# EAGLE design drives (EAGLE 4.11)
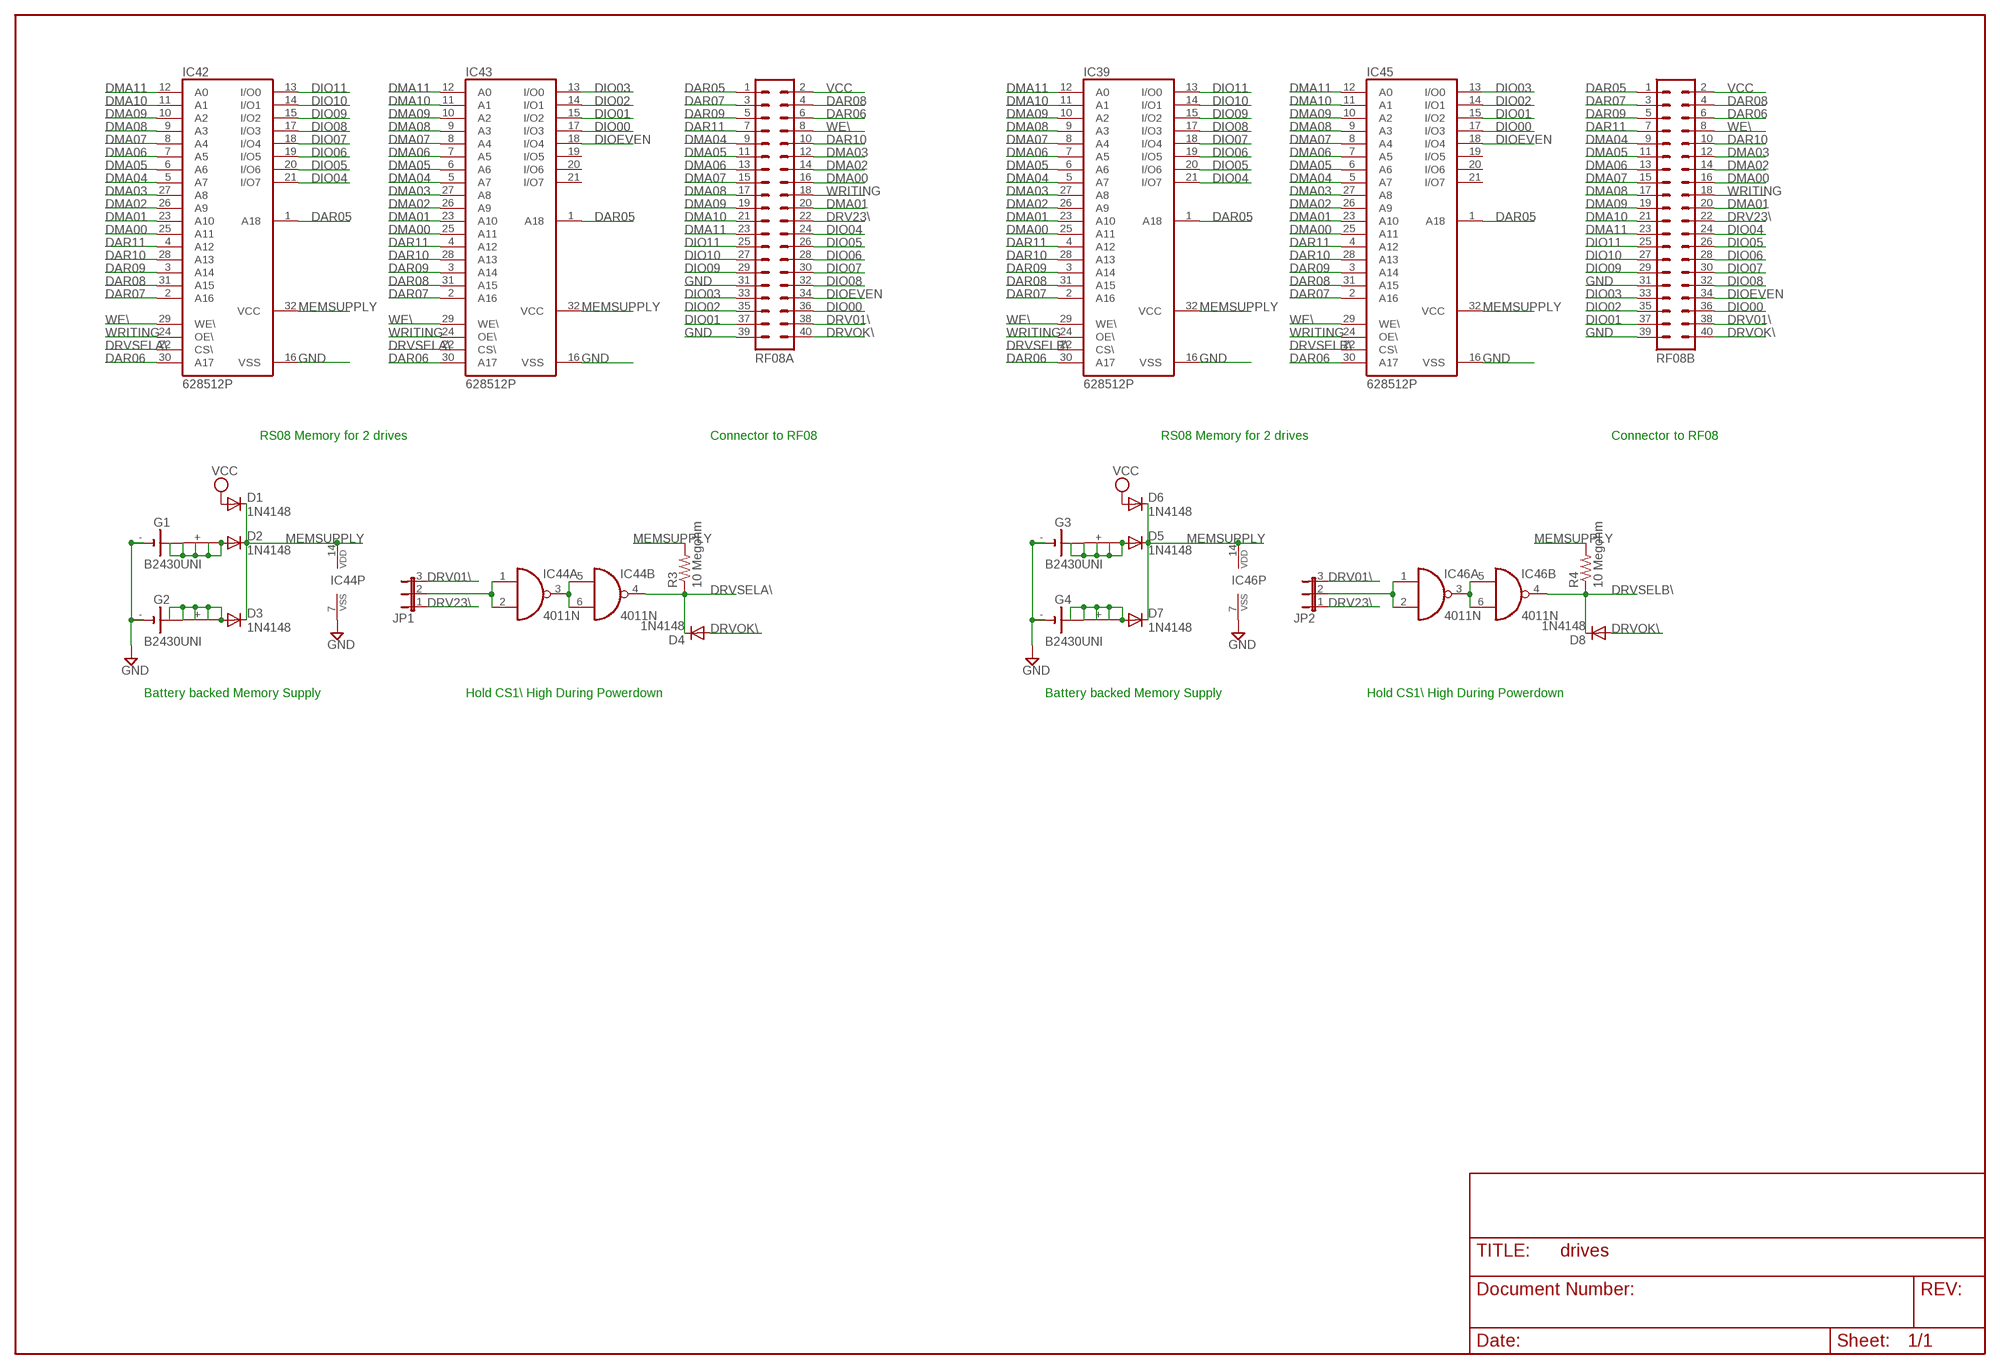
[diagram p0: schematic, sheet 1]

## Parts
D1  1N4148  [DO35-10]
D2  1N4148  [DO35-10]
D3  1N4148  [DO35-10]
D4  1N4148  [DO35-10]
D5  1N4148  [DO35-10]
D6  1N4148  [DO35-10]
D7  1N4148  [DO35-10]
D8  1N4148  [DO35-10]
G1  B2430UNI  [B2430UNI]
G2  B2430UNI  [B2430UNI]
G3  B2430UNI  [B2430UNI]
G4  B2430UNI  [B2430UNI]
IC39  628512P  [DIL32]
IC42  628512P  [DIL32]
IC43  628512P  [DIL32]
IC44  4011N  [DIL14]
IC45  628512P  [DIL32]
IC46  4011N  [DIL14]
JP1  JP2E  [JP2]
JP2  JP2E  [JP2]
R3  10 Megohm  R-US_0207/10  [0207/10]
R4  10 Megohm  R-US_0207/10  [0207/10]
RF08A  MA20-2  [MA20-2]
RF08B  MA20-2  [MA20-2]

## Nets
DAR05: IC39.1(A18) IC42.1(A18) IC43.1(A18) IC45.1(A18) RF08A.1 RF08B.1
DAR06: IC39.30(A17) IC42.30(A17) IC43.30(A17) IC45.30(A17) RF08A.6 RF08B.6
DAR07: IC39.2(A16) IC42.2(A16) IC43.2(A16) IC45.2(A16) RF08A.3 RF08B.3
DAR08: IC39.31(A15) IC42.31(A15) IC43.31(A15) IC45.31(A15) RF08A.4 RF08B.4
DAR09: IC39.3(A14) IC42.3(A14) IC43.3(A14) IC45.3(A14) RF08A.5 RF08B.5
DAR10: IC39.28(A13) IC42.28(A13) IC43.28(A13) IC45.28(A13) RF08A.10 RF08B.10
DAR11: IC39.4(A12) IC42.4(A12) IC43.4(A12) IC45.4(A12) RF08A.7 RF08B.7
DIO00: IC43.17(I/O3) IC45.17(I/O3) RF08A.36 RF08B.36
DIO01: IC43.15(I/O2) IC45.15(I/O2) RF08A.37 RF08B.37
DIO02: IC43.14(I/O1) IC45.14(I/O1) RF08A.35 RF08B.35
DIO03: IC43.13(I/O0) IC45.13(I/O0) RF08A.33 RF08B.33
DIO04: IC39.21(I/O7) IC42.21(I/O7) RF08A.24 RF08B.24
DIO05: IC39.20(I/O6) IC42.20(I/O6) RF08A.26 RF08B.26
DIO06: IC39.19(I/O5) IC42.19(I/O5) RF08A.28 RF08B.28
DIO07: IC39.18(I/O4) IC42.18(I/O4) RF08A.30 RF08B.30
DIO08: IC39.17(I/O3) IC42.17(I/O3) RF08A.32 RF08B.32
DIO09: IC39.15(I/O2) IC42.15(I/O2) RF08A.29 RF08B.29
DIO10: IC39.14(I/O1) IC42.14(I/O1) RF08A.27 RF08B.27
DIO11: IC39.13(I/O0) IC42.13(I/O0) RF08A.25 RF08B.25
DIOEVEN: IC43.18(I/O4) IC45.18(I/O4) RF08A.34 RF08B.34
DMA00: IC39.25(A11) IC42.25(A11) IC43.25(A11) IC45.25(A11) RF08A.16 RF08B.16
DMA01: IC39.23(A10) IC42.23(A10) IC43.23(A10) IC45.23(A10) RF08A.20 RF08B.20
DMA02: IC39.26(A9) IC42.26(A9) IC43.26(A9) IC45.26(A9) RF08A.14 RF08B.14
DMA03: IC39.27(A8) IC42.27(A8) IC43.27(A8) IC45.27(A8) RF08A.12 RF08B.12
DMA04: IC39.5(A7) IC42.5(A7) IC43.5(A7) IC45.5(A7) RF08A.9 RF08B.9
DMA05: IC39.6(A6) IC42.6(A6) IC43.6(A6) IC45.6(A6) RF08A.11 RF08B.11
DMA06: IC39.7(A5) IC42.7(A5) IC43.7(A5) IC45.7(A5) RF08A.13 RF08B.13
DMA07: IC39.8(A4) IC42.8(A4) IC43.8(A4) IC45.8(A4) RF08A.15 RF08B.15
DMA08: IC39.9(A3) IC42.9(A3) IC43.9(A3) IC45.9(A3) RF08A.17 RF08B.17
DMA09: IC39.10(A2) IC42.10(A2) IC43.10(A2) IC45.10(A2) RF08A.19 RF08B.19
DMA10: IC39.11(A1) IC42.11(A1) IC43.11(A1) IC45.11(A1) RF08A.21 RF08B.21
DMA11: IC39.12(A0) IC42.12(A0) IC43.12(A0) IC45.12(A0) RF08A.23 RF08B.23
DRV01\: JP1.3 JP2.3 RF08A.38 RF08B.38
DRV23\: JP1.1 JP2.1 RF08A.22 RF08B.22
DRVOK\: D4.A D8.A RF08A.40 RF08B.40
DRVSELA\: D4.C IC42.22(CS\) IC43.22(CS\) IC44.4(B:O) R3.1
DRVSELB\: D8.C IC39.22(CS\) IC45.22(CS\) IC46.4(B:O) R4.1
GND: G1.- G1.-@1(-) G2.- G2.-@1(-) G3.- G3.-@1(-) G4.- G4.-@1(-) IC39.16(VSS) IC42.16(VSS) IC43.16(VSS) IC44.7(P:VSS) IC45.16(VSS) IC46.7(P:VSS) RF08A.31 RF08A.39 RF08B.31 RF08B.39
MEMSUPPLY [Power]: D1.C D2.C D3.C D5.C D6.C D7.C IC39.32(VCC) IC42.32(VCC) IC43.32(VCC) IC44.14(P:VDD) IC45.32(VCC) IC46.14(P:VDD) R3.2 R4.2
N$18: IC44.3(A:O) IC44.5(B:I0) IC44.6(B:I1)
N$35: IC44.1(A:I0) IC44.2(A:I1) JP1.2
N$36: D7.A G4.+ G4.+@1(+) G4.+@2(+) G4.+@3(+) G4.+@4(+)
N$38: IC46.3(A:O) IC46.5(B:I0) IC46.6(B:I1)
N$39: IC46.1(A:I0) IC46.2(A:I1) JP2.2
N$41: D5.A G3.+ G3.+@1(+) G3.+@2(+) G3.+@3(+) G3.+@4(+)
N$130: D3.A G2.+ G2.+@1(+) G2.+@2(+) G2.+@3(+) G2.+@4(+)
N$131: D2.A G1.+ G1.+@1(+) G1.+@2(+) G1.+@3(+) G1.+@4(+)
VCC [Power]: D1.A D6.A RF08A.2 RF08B.2
WE\: IC39.29(WE\) IC42.29(WE\) IC43.29(WE\) IC45.29(WE\) RF08A.8 RF08B.8
WRITING: IC39.24(OE\) IC42.24(OE\) IC43.24(OE\) IC45.24(OE\) RF08A.18 RF08B.18
Unconnected: IC43.19(I/O5) IC43.20(I/O6) IC43.21(I/O7) IC44.8(C:I0) IC44.9(C:I1) IC44.10(C:O) IC44.11(D:O) IC44.12(D:I0) IC44.13(D:I1) IC45.19(I/O5) IC45.20(I/O6) IC45.21(I/O7) IC46.8(C:I0) IC46.9(C:I1) IC46.10(C:O) IC46.11(D:O) IC46.12(D:I0) IC46.13(D:I1)

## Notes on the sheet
- RS08 Memory for 2 drives | Connector to RF08 | RS08 Memory for 2 drives | Connector to RF08
- Battery backed Memory Supply | Hold CS1\ High During Powerdown | Battery backed Memory Supply | Hold CS1\ High During Powerdown

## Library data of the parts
D1-D8 = diode:1N4148: DIODE
G1-G4 = battery:B2430UNI: LI BATTERY
IC39 IC42 IC43 IC45 = memory-hitachi:628512P: 512Kx8 Static RAM
IC44 IC46 = 40xx:4011: Quad 2-input NAND
JP1 JP2 = jumper:JP2E: JUMPER
R3 R4 = rcl:R-US_: RESISTOR, American symbol
RF08A RF08B = con-lstb:MA20-2: PIN HEADER

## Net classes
1 Power: width 0.508 mm

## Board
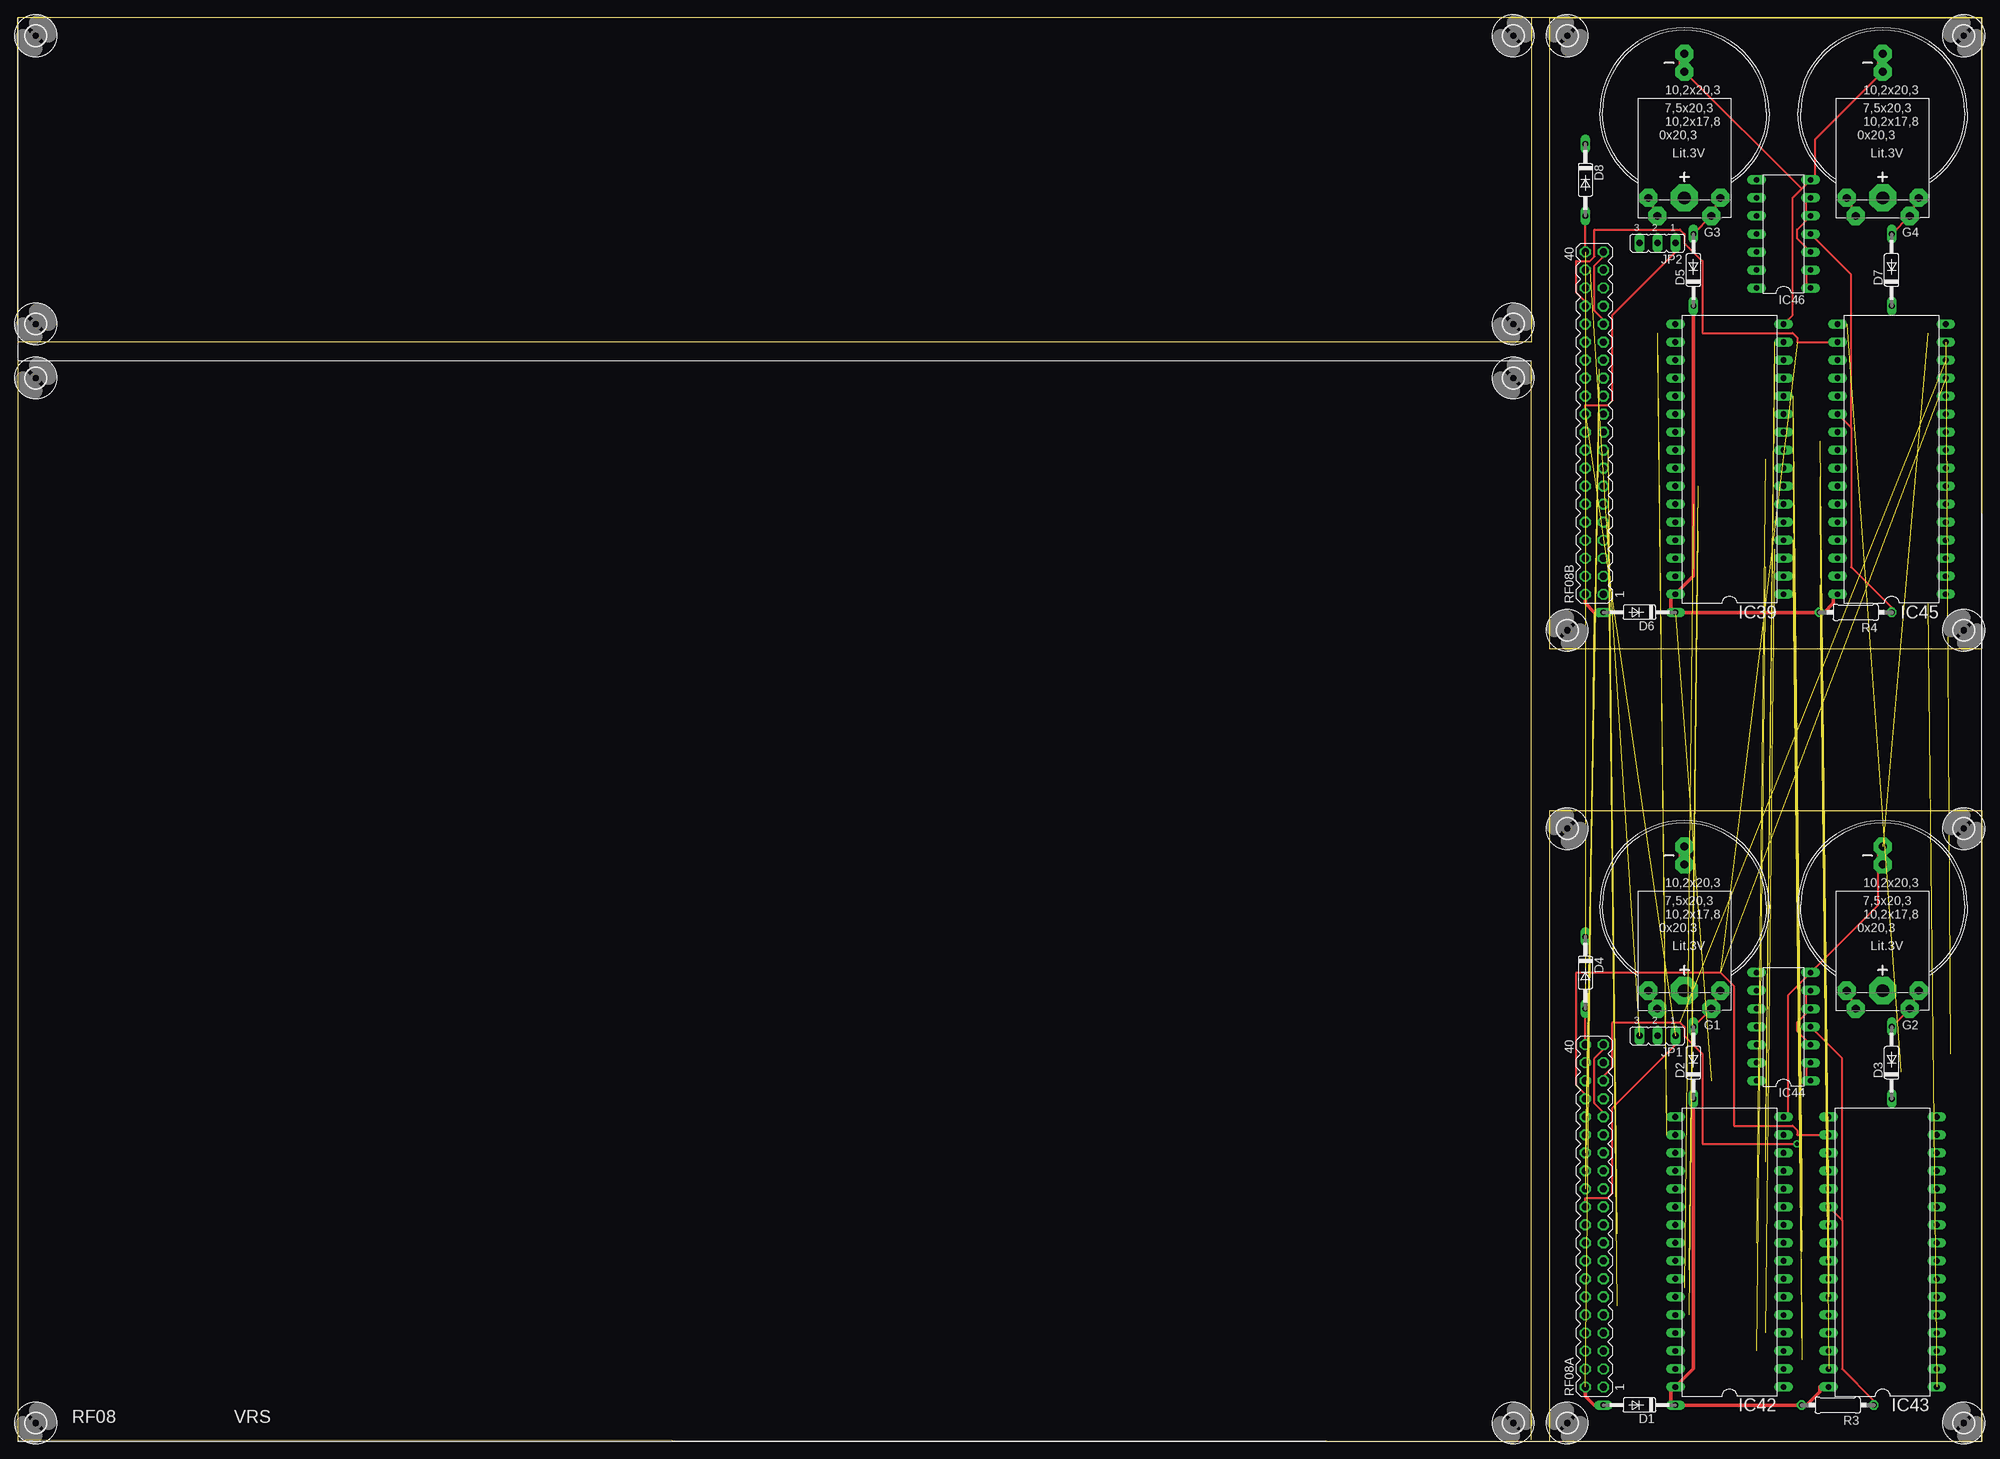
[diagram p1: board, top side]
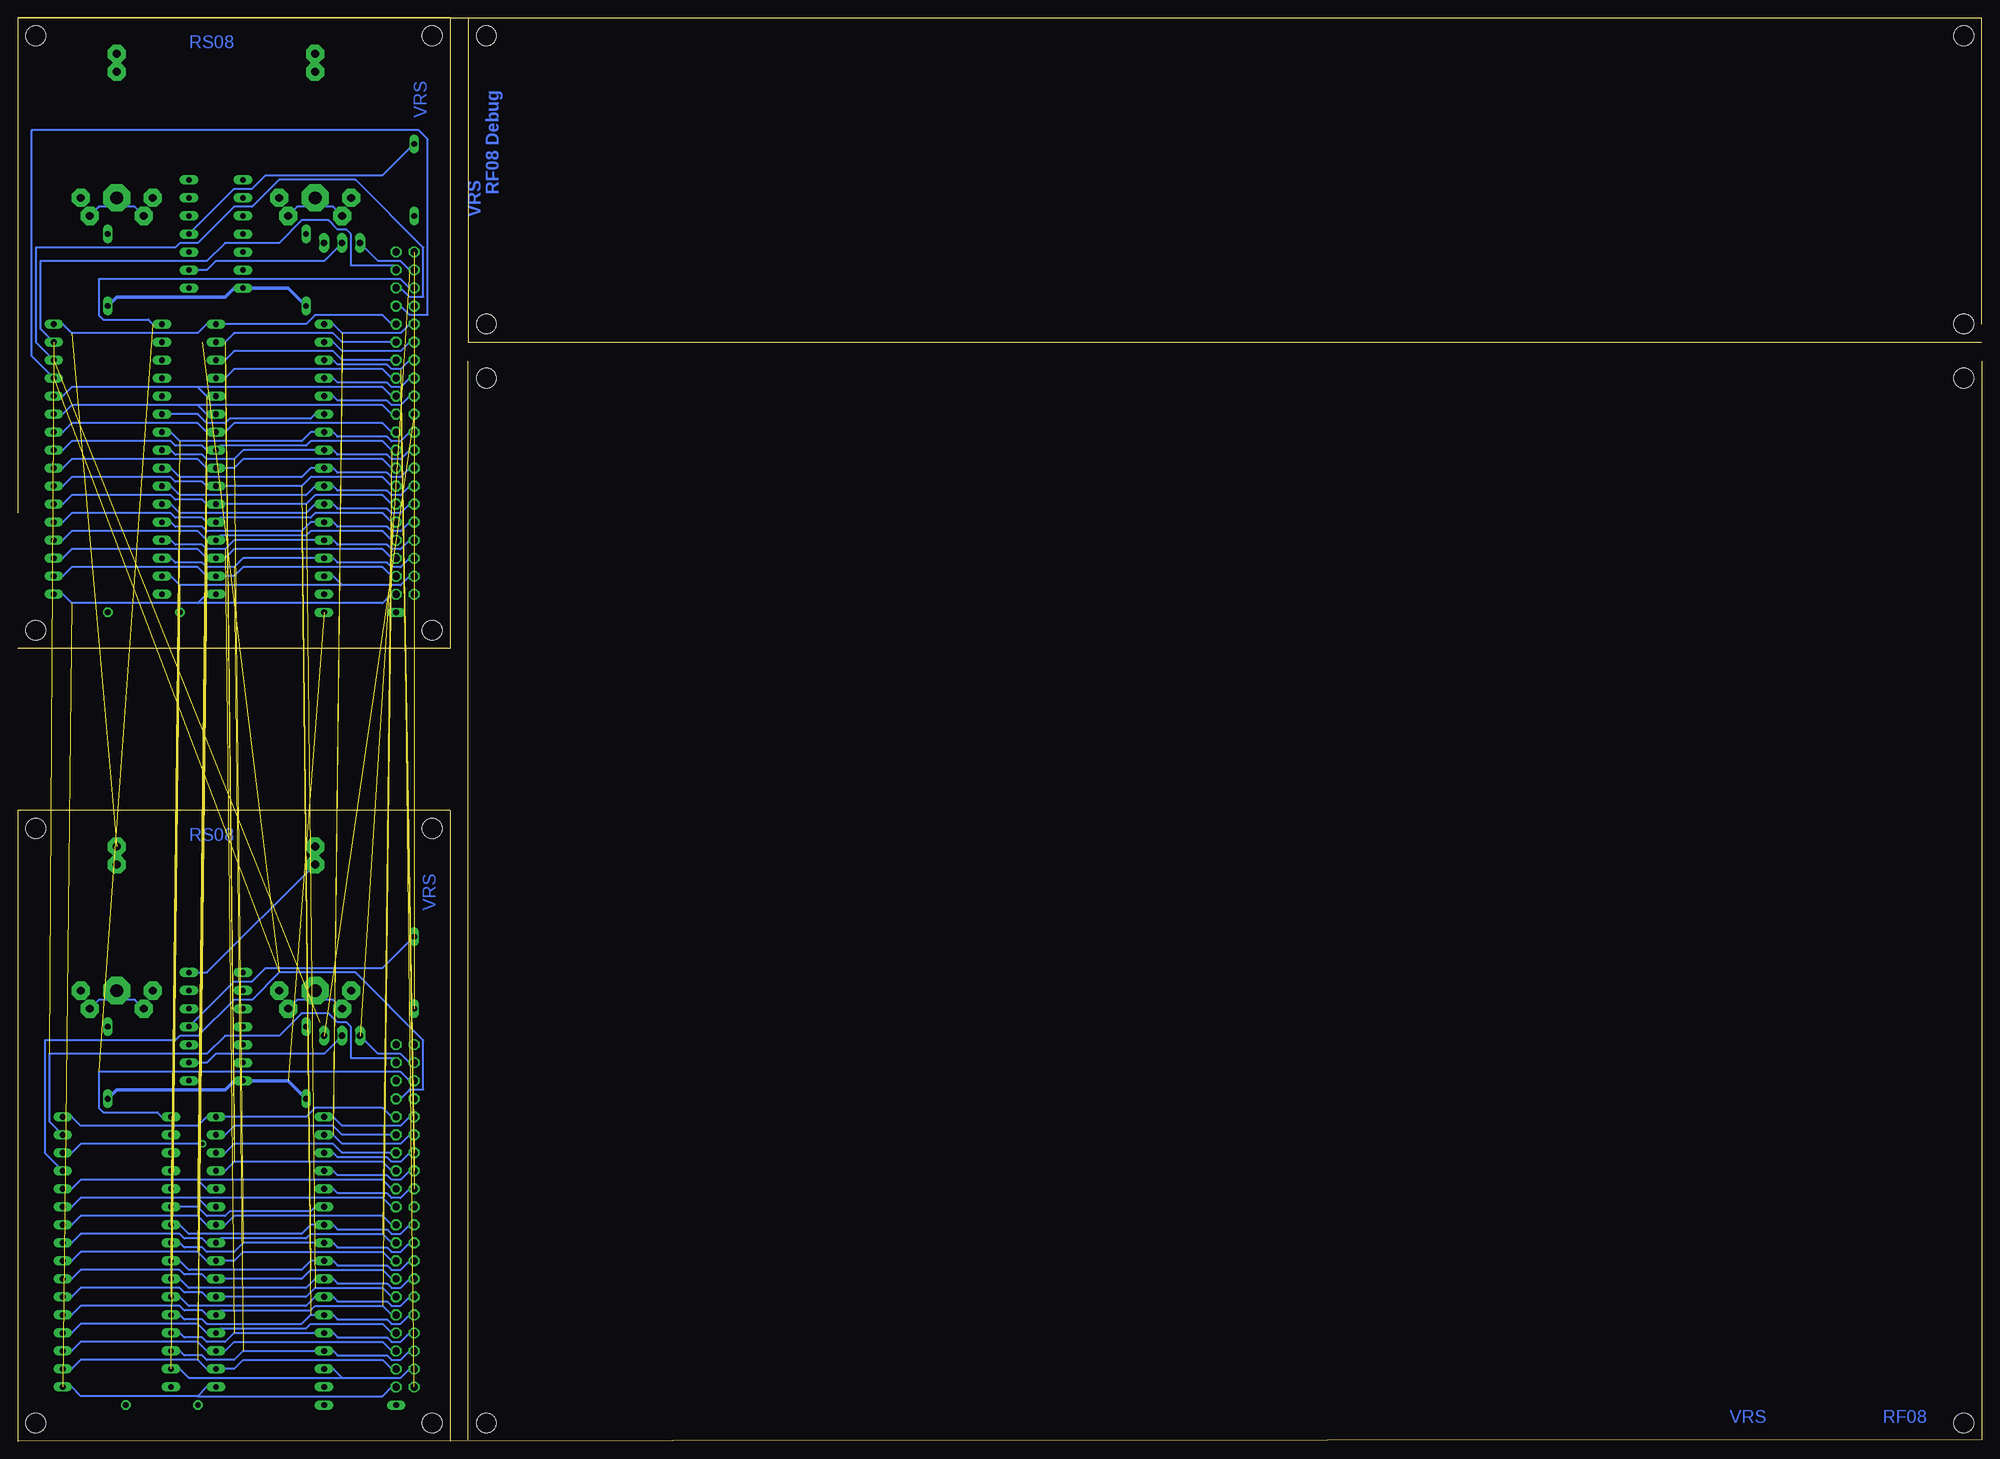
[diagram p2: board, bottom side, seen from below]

Size 276.86 x 200.67 mm. Coordinates in mm from the lower left corner, seen from the top.
Outline: 276.69,0 0.01,0.18 0.01,152.25
Outline: 213.34,0.18 213.34,152.25
Outline: 215.9,0.01 215.9,88.92 276.86,88.92 276.86,0.01
Outline: 276.86,111.78 215.9,111.78 215.9,200.67 276.86,200.67
Outline: 276.86,200.67 0,200.67 0,157.49
Outline: 276.86,200.67 276.86,130.82
Outline: 0,154.95 213.36,154.95 213.36,200.67
Copper layers (1*16): Top 0.035mm / dielectric 1.5mm / Bottom 0.035mm
Design rules "olimex10mil": minimum track width 10mil, minimum drill 24mil, track to track 10mil, track to pad 10mil, pad to pad 10mil, via to via 10mil, smd to smd 10mil, copper to edge 40mil, drill to drill 10mil, minimum pad ring 10mil, minimum via ring 8mil, stop-mask expansion 0mil, vias tented up to drill 0mil, thermal gap 10mil

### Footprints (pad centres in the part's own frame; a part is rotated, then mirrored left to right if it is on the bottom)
DO35-10 = drill 0.813 long: A 5.08,0; C -5.08,0
B2430UNI = drill 1.118 pad 2.54 octagon: + 3.81,14.605; +@1 -3.81,14.605; +@2 -5.08,12.065; +@3 5.08,12.065; - 0,-5.715; -@1 0,-8.255 | drill 1.803 pad 3.81 octagon: +@4 0,12.065
DIL32 = drill 0.813 long: 1 -19.05,-7.62; 2 -16.51,-7.62; 3 -13.97,-7.62; 4 -11.43,-7.62; 5 -8.89,-7.62; 6 -6.35,-7.62; 7 -3.81,-7.62; 8 -1.27,-7.62; 9 1.27,-7.62; 10 3.81,-7.62; 11 6.35,-7.62; 12 8.89,-7.62; 13 11.43,-7.62; 14 13.97,-7.62; 15 16.51,-7.62; 16 19.05,-7.62; 17 19.05,7.62; 18 16.51,7.62; 19 13.97,7.62; 20 11.43,7.62; 21 8.89,7.62; 22 6.35,7.62; 23 3.81,7.62; 24 1.27,7.62; 25 -1.27,7.62; 26 -3.81,7.62; 27 -6.35,7.62; 28 -8.89,7.62; 29 -11.43,7.62; 30 -13.97,7.62; 31 -16.51,7.62; 32 -19.05,7.62
DIL14 = drill 0.813 long: 1 -7.62,-3.81; 2 -5.08,-3.81; 3 -2.54,-3.81; 4 0,-3.81; 5 2.54,-3.81; 6 5.08,-3.81; 7 7.62,-3.81; 8 7.62,3.81; 9 5.08,3.81; 10 2.54,3.81; 11 0,3.81; 12 -2.54,3.81; 13 -5.08,3.81; 14 -7.62,3.81
JP2 = drill 0.914 long: 1 -2.54,0; 2 0,0; 3 2.54,0
0207/10 = drill 0.813 octagon: 1 -5.08,0; 2 5.08,0
MA20-2 = drill 1.016 octagon: 1 -24.13,-1.27; 2 -24.13,1.27; 3 -21.59,-1.27; 4 -21.59,1.27; 5 -19.05,-1.27; 6 -19.05,1.27; 7 -16.51,-1.27; 8 -16.51,1.27; 9 -13.97,-1.27; 10 -13.97,1.27; 11 -11.43,-1.27; 12 -11.43,1.27; 13 -8.89,-1.27; 14 -8.89,1.27; 15 -6.35,-1.27; 16 -6.35,1.27; 17 -3.81,-1.27; 18 -3.81,1.27; 19 -1.27,-1.27; 20 -1.27,1.27; 21 1.27,-1.27; 22 1.27,1.27; 23 3.81,-1.27; 24 3.81,1.27; 25 6.35,-1.27; 26 6.35,1.27; 27 8.89,-1.27; 28 8.89,1.27; 29 11.43,-1.27; 30 11.43,1.27; 31 13.97,-1.27; 32 13.97,1.27; 33 16.51,-1.27; 34 16.51,1.27; 35 19.05,-1.27; 36 19.05,1.27; 37 21.59,-1.27; 38 21.59,1.27; 39 24.13,-1.27; 40 24.13,1.27
2,8 = hole 2.8: 0,0

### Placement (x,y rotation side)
D1  228.6,5.09 180 top
D2  236.22,53.36 90 top
D3  264.16,53.36 90 top
D4  220.98,66.06 270 top
D5  236.22,165.11 90 top
D6  228.6,116.86 180 top
D7  264.16,165.11 90 top
D8  220.98,177.81 270 top
G1  234.95,75.58 180 top
G2  262.89,75.58 180 top
G3  234.95,187.34 180 top
G4  262.89,187.34 180 top
IC39  241.3,138.44 90 top
IC42  241.3,26.69 90 top
IC43  262.89,26.69 90 top
IC44  248.92,58.44 90 top
IC45  264.16,138.44 90 top
IC46  248.92,170.19 90 top
JP1  231.14,57.16 180 top
JP2  231.14,168.92 180 top
R3  256.54,5.09 180 top
R4  259.08,116.86 180 top
RF08A  222.25,31.77 90 top
RF08B  222.25,143.52 90 top
U$1  [2,8]  2.54,149.88 0 top
U$2  [2,8]  210.82,149.88 0 top
U$3  [2,8]  2.54,2.56 0 top
U$4  [2,8]  210.82,2.56 0 top
U$5  [2,8]  274.32,2.56 90 top
U$6  [2,8]  218.44,2.56 90 top
U$7  [2,8]  218.44,86.38 90 top
U$8  [2,8]  274.32,86.38 90 top
U$9  [2,8]  274.32,198.13 90 top
U$10  [2,8]  274.32,114.31 90 top
U$11  [2,8]  218.44,114.31 90 top
U$12  [2,8]  218.44,198.13 90 top
U$13  [2,8]  2.54,157.49 0 top
U$14  [2,8]  2.54,198.13 0 top
U$16  [2,8]  210.82,157.49 0 top
U$17  [2,8]  210.82,198.13 0 top
U$18  [SIERRA-PROTO]  0,0.01 0 top

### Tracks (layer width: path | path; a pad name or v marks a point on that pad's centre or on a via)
DAR05  (1 unrouted)
  Bottom 0.254: 251.46,118.12 250.19,119.39 IC39.1 | 251.46,118.12 269.24,118.12 270.51,119.39 IC45.1 | 251.46,118.12 225.43,118.12 224.16,119.39 RF08B.1 | 251.46,6.36 250.19,7.63 IC42.1 | 251.46,6.36 267.97,6.36 269.24,7.63 IC43.1 | 251.46,6.36 225.43,6.36 224.16,7.63 RF08A.1
DAR06  (1 unrouted)
  Bottom 0.254: RF08A.6 221.62,12.71 222.88,11.45 224.16,11.45 224.79,12.08 231.78,12.08 232.41,12.71 IC42.30 245.11,12.71 246.38,11.45 250.19,11.45 250.82,12.08 253.37,12.08 254,12.71 IC43.30 | RF08B.6 221.62,124.47 222.88,123.2 224.16,123.2 224.79,123.84 231.78,123.84 232.41,124.47 IC39.30 245.11,124.47 246.38,123.2 250.19,123.2 250.82,123.84 254.63,123.84 255.27,124.47 IC45.30
DAR07  (1 unrouted)
  Bottom 0.254: IC43.2 269.24,10.18 267.97,11.45 251.46,11.45 250.19,10.18 IC42.2 246.38,10.18 245.11,11.45 225.43,11.45 224.16,10.18 RF08A.3 | IC45.2 270.51,121.94 269.24,123.2 251.46,123.2 250.19,121.94 IC39.2 246.38,121.94 245.11,123.2 225.43,123.2 224.16,121.94 RF08B.3
DAR08  (1 unrouted)
  Bottom 0.254: 231.14,8.91 232.41,10.18 IC42.31 | 231.14,8.91 222.88,8.91 221.62,10.18 RF08A.4 | 231.14,8.91 252.73,8.91 254,10.18 IC43.31 | 231.14,120.67 232.41,121.94 IC39.31 | 231.14,120.67 222.88,120.67 221.62,121.94 RF08B.4 | 231.14,120.67 254,120.67 255.27,121.94 IC45.31
DAR09  (1 unrouted)
  Bottom 0.254: IC45.3 270.51,124.47 269.24,125.75 251.46,125.75 250.19,124.47 IC39.3 247.65,124.47 246.38,125.75 225.43,125.75 224.16,124.47 RF08B.5 | IC43.3 269.24,12.71 267.97,13.99 251.46,13.99 250.19,12.71 IC42.3 247.65,12.71 246.38,13.99 225.43,13.99 224.16,12.71 RF08A.5
DAR10  (1 unrouted)
  Bottom 0.254: RF08A.10 221.62,17.8 222.88,16.53 224.16,16.53 224.79,17.16 231.78,17.16 232.41,17.8 IC42.28 235.59,17.8 236.85,16.53 250.19,16.53 250.82,17.16 253.37,17.16 254,17.8 IC43.28 | RF08B.10 221.62,129.55 222.88,128.28 224.16,128.28 224.79,128.92 231.78,128.92 232.41,129.55 IC39.28 235.59,129.55 236.85,128.28 250.19,128.28 250.82,128.92 254.63,128.92 255.27,129.55 IC45.28
DAR11  (1 unrouted)
  Bottom 0.254: IC45.4 270.51,127.02 269.24,128.28 251.46,128.28 250.19,127.02 IC39.4 248.28,127.65 236.22,127.65 235.59,128.28 225.43,128.28 224.16,127.02 RF08B.7 | IC43.4 269.24,15.26 267.97,16.53 251.46,16.53 250.19,15.26 IC42.4 248.28,15.89 236.22,15.89 235.59,16.53 225.43,16.53 224.16,15.26 RF08A.7
DIO00  (1 unrouted)
  Bottom 0.254: IC43.17 256.54,45.73 257.18,46.37 264.8,46.37 265.43,47.01 265.43,52.09 222.88,52.09 221.62,50.81 RF08A.36 | IC45.17 257.81,157.49 258.44,158.13 264.8,158.13 265.43,158.76 265.43,163.84 222.88,163.84 221.62,162.57 RF08B.36
DIO01  (1 unrouted)
  Bottom 0.254: IC43.15 272.42,45.1 272.42,54.62 250.19,54.62 247.65,57.16 240.03,57.16 236.85,60.34 233.04,60.34 231.78,59.07 230.5,59.07 229.87,58.44 229.87,53.99 223.52,53.99 RF08A.37 | IC45.15 273.69,156.86 273.69,166.38 250.19,166.38 247.65,168.92 240.03,168.92 236.85,172.1 233.04,172.1 231.78,170.83 230.5,170.83 229.87,170.19 229.87,165.75 223.52,165.75 RF08B.37
DIO02  (via drill 0.61)  (1 unrouted)
  Top 0.254: v250.82,41.92 237.49,41.92 237.49,54.62 234.95,57.16 234.95,58.44 234.31,59.07 224.79,59.07 224.79,52.72 223.52,51.45 RF08A.35
  Bottom 0.254: v250.82,41.92 267.97,41.92 269.24,40.66 IC43.14 | IC45.14 274.32,154.95 274.32,168.29 254.63,168.29 254,168.92 251.46,168.92 246.38,174 243.84,174 240.03,177.81 229.24,177.81 219.71,168.29 219.71,161.3 221.62,161.3 222.88,162.57 RF08B.35
DIO03  (1 unrouted)
  Bottom 0.254: IC43.13 273.05,40.66 273.05,56.53 254.63,56.53 254,57.16 251.46,57.16 246.38,62.24 243.84,62.24 240.03,66.06 229.24,66.06 219.71,56.53 219.71,49.55 221.62,49.55 222.88,48.27 RF08A.33 | IC45.13 274.95,153.05 274.95,184.8 220.34,184.8 219.07,183.53 219.07,158.76 221.62,158.76 222.88,160.03 RF08B.33
DIO04  (1 unrouted)
  Bottom 0.254: IC42.21 232.41,35.58 231.78,34.94 224.79,34.94 224.16,34.3 222.88,34.3 221.62,35.58 RF08A.24 | IC39.21 232.41,147.33 231.78,146.7 224.79,146.7 224.16,146.06 222.88,146.06 221.62,147.33 RF08B.24
DIO05  (1 unrouted)
  Bottom 0.254: IC42.20 232.41,38.12 231.78,37.48 224.79,37.48 224.16,36.84 222.88,36.84 221.62,38.12 RF08A.26 | IC39.20 232.41,149.88 231.78,149.24 224.79,149.24 224.16,148.6 222.88,148.6 221.62,149.88 RF08B.26
DIO06  (1 unrouted)
  Bottom 0.254: IC42.19 232.41,40.66 231.78,40.02 224.79,40.02 224.16,39.38 222.88,39.38 221.62,40.66 RF08A.28 | IC39.19 232.41,152.41 231.78,151.78 224.79,151.78 224.16,151.14 222.88,151.14 221.62,152.41 RF08B.28
DIO07  (1 unrouted)
  Bottom 0.254: IC42.18 232.41,43.2 231.14,41.92 222.88,41.92 221.62,43.2 RF08A.30 | IC39.18 232.41,154.95 231.14,153.68 222.88,153.68 221.62,154.95 RF08B.30
DIO08  (1 unrouted)
  Bottom 0.254: IC42.17 232.41,45.73 231.14,44.47 222.88,44.47 221.62,45.73 RF08A.32 | IC39.17 232.41,157.49 231.14,156.22 222.88,156.22 221.62,157.49 RF08B.32
DIO09  (1 unrouted)
  Bottom 0.254: IC42.15 247.65,43.2 246.38,44.47 232.41,44.47 231.14,43.2 RF08A.29 | IC39.15 247.65,154.95 246.38,156.22 232.41,156.22 231.14,154.95 RF08B.29
DIO10  (1 unrouted)
  Bottom 0.254: IC42.14 247.65,40.66 246.38,41.92 232.41,41.92 231.14,40.66 RF08A.27 | IC39.14 247.65,152.41 246.38,153.68 232.41,153.68 231.14,152.41 RF08B.27
DIO11  (1 unrouted)
  Bottom 0.254: IC42.13 247.65,38.12 246.38,39.38 225.43,39.38 224.16,38.12 RF08A.25 | IC39.13 247.65,149.88 246.38,151.14 225.43,151.14 224.16,149.88 RF08B.25
DIOEVEN  (1 unrouted)
  Top 0.254: IC43.18 250.82,43.2 250.82,43.83 250.19,44.47 241.94,44.47 241.94,64.15 240.03,66.06 219.71,66.06 219.71,50.18 220.98,48.91 RF08A.34 | IC45.18 250.82,154.95 250.82,155.59 250.19,156.22 237.49,156.22 237.49,166.38 234.95,168.92 234.95,170.19 234.31,170.83 222.25,170.83 222.25,167.02 221.62,166.38 219.71,166.38 219.71,161.94 220.98,160.67 RF08B.34
DMA00  (1 unrouted)
  Bottom 0.254: RF08A.16 221.62,25.41 222.88,24.14 224.16,24.14 224.79,24.78 231.78,24.78 232.41,25.41 IC42.25 235.59,25.41 236.85,24.14 252.73,24.14 254,25.41 IC43.25 | RF08B.16 221.62,137.17 222.88,135.9 224.16,135.9 224.79,136.54 231.78,136.54 232.41,137.17 IC39.25 235.59,137.17 236.85,135.9 254,135.9 255.27,137.17 IC45.25
DMA01  (1 unrouted)
  Bottom 0.254: RF08A.20 221.62,30.5 222.88,29.23 224.16,29.23 224.79,29.86 231.78,29.86 232.41,30.5 IC42.23 235.59,30.5 236.85,29.23 252.73,29.23 254,30.5 IC43.23 | RF08B.20 221.62,142.25 222.88,140.98 224.16,140.98 224.79,141.62 231.78,141.62 232.41,142.25 IC39.23 235.59,142.25 236.85,140.98 254,140.98 255.27,142.25 IC45.23
DMA02  (1 unrouted)
  Bottom 0.254: RF08A.14 221.62,22.88 222.88,21.61 224.16,21.61 224.79,22.24 231.78,22.24 232.41,22.88 IC42.26 234.95,22.88 236.22,21.61 252.73,21.61 254,22.88 IC43.26 | RF08B.14 221.62,134.63 222.88,133.36 224.16,133.36 224.79,134 231.78,134 232.41,134.63 IC39.26 234.95,134.63 236.22,133.36 254,133.36 255.27,134.63 IC45.26
DMA03  (1 unrouted)
  Bottom 0.254: RF08A.12 221.62,20.34 222.88,19.07 224.16,19.07 224.79,19.7 231.78,19.7 232.41,20.34 IC42.27 234.95,20.34 236.22,19.07 252.73,19.07 254,20.34 IC43.27 | RF08B.12 221.62,132.09 222.88,130.82 224.16,130.82 224.79,131.46 231.78,131.46 232.41,132.09 IC39.27 234.95,132.09 236.22,130.82 254,130.82 255.27,132.09 IC45.27
DMA04  (1 unrouted)
  Bottom 0.254: IC43.5 269.24,17.8 267.97,19.07 254,19.07 253.37,18.43 250.82,18.43 250.19,17.8 IC42.5 248.28,18.43 235.59,18.43 234.95,19.07 225.43,19.07 224.16,17.8 RF08A.9 | IC45.5 270.51,129.55 269.24,130.82 255.27,130.82 254.63,130.19 250.82,130.19 250.19,129.55 IC39.5 248.28,130.19 235.59,130.19 234.95,130.82 225.43,130.82 224.16,129.55 RF08B.9
DMA05  (1 unrouted)
  Bottom 0.254: IC45.6 270.51,132.09 269.24,133.36 255.27,133.36 254.63,132.73 250.82,132.73 250.19,132.09 IC39.6 236.22,132.09 234.95,133.36 225.43,133.36 224.16,132.09 RF08B.11 | IC43.6 269.24,20.34 267.97,21.61 254,21.61 253.37,20.97 250.82,20.97 250.19,20.34 IC42.6 236.22,20.34 234.95,21.61 225.43,21.61 224.16,20.34 RF08A.11
DMA06  (1 unrouted)
  Bottom 0.254: IC45.7 270.51,134.63 269.24,135.9 255.27,135.9 254.63,135.27 250.82,135.27 250.19,134.63 IC39.7 236.85,134.63 235.59,135.9 225.43,135.9 224.16,134.63 RF08B.13 | IC43.7 269.24,22.88 267.97,24.14 254,24.14 253.37,23.51 250.82,23.51 250.19,22.88 IC42.7 236.85,22.88 235.59,24.14 225.43,24.14 224.16,22.88 RF08A.13
DMA07  (1 unrouted)
  Bottom 0.254: IC45.8 270.51,137.17 269.24,138.44 251.46,138.44 250.19,137.17 IC39.8 246.38,137.17 245.11,138.44 225.43,138.44 224.16,137.17 RF08B.15 | IC43.8 269.24,25.41 267.97,26.69 251.46,26.69 250.19,25.41 IC42.8 246.38,25.41 245.11,26.69 225.43,26.69 224.16,25.41 RF08A.15
DMA08  (1 unrouted)
  Bottom 0.254: IC45.9 270.51,139.71 269.24,140.98 255.27,140.98 254.63,140.35 250.82,140.35 250.19,139.71 IC39.9 248.28,140.35 236.22,140.35 235.59,140.98 225.43,140.98 224.16,139.71 RF08B.17 | IC43.9 269.24,27.96 267.97,29.23 254,29.23 253.37,28.59 250.82,28.59 250.19,27.96 IC42.9 248.28,28.59 236.22,28.59 235.59,29.23 225.43,29.23 224.16,27.96 RF08A.17
DMA09  (1 unrouted)
  Bottom 0.254: IC45.10 270.51,142.25 269.24,143.52 251.46,143.52 250.19,142.25 IC39.10 247.65,142.25 246.38,143.52 225.43,143.52 224.16,142.25 RF08B.19 | IC43.10 269.24,30.5 267.97,31.77 251.46,31.77 250.19,30.5 IC42.10 247.65,30.5 246.38,31.77 225.43,31.77 224.16,30.5 RF08A.19
DMA10  (1 unrouted)
  Bottom 0.254: 251.46,146.06 250.19,144.79 IC39.11 | 251.46,146.06 269.24,146.06 270.51,144.79 IC45.11 | 251.46,146.06 225.43,146.06 224.16,144.79 RF08B.21 | 251.46,34.3 250.19,33.04 IC42.11 | 251.46,34.3 267.97,34.3 269.24,33.04 IC43.11 | 251.46,34.3 225.43,34.3 224.16,33.04 RF08A.21
DMA11  (1 unrouted)
  Bottom 0.254: 251.46,148.6 250.19,147.33 IC39.12 | 251.46,148.6 269.24,148.6 270.51,147.33 IC45.12 | 251.46,148.6 225.43,148.6 224.16,147.33 RF08B.23 | 251.46,36.84 250.19,35.58 IC42.12 | 251.46,36.84 267.97,36.84 269.24,35.58 IC43.12 | 251.46,36.84 225.43,36.84 224.16,35.58 RF08A.23
DRV01\  (1 unrouted)
  Bottom 0.254: JP1.3 226.06,54.62 222.88,54.62 221.62,53.36 RF08A.38 | JP2.3 226.06,166.38 222.88,166.38 221.62,165.11 RF08B.38
DRV23\  (1 unrouted)
  Top 0.254: JP1.1 233.68,55.9 224.79,47.01 224.79,34.94 224.16,34.3 220.98,34.3 RF08A.22 | JP2.1 233.68,167.65 224.79,158.76 224.79,146.7 224.16,146.06 220.98,146.06 RF08B.22
DRVOK\  (1 unrouted)
  Top 0.254: RF08A.40 D4.A | RF08B.40 D8.A
DRVSELA\
  Top 0.254: 257.18,31.13 257.18,10.18 261.62,5.73 R3.1 | IC43.22 257.18,31.13 | 257.18,31.13 257.18,53.99 IC44.4
  Bottom 0.254: IC42.22 234.95,33.04 235.59,32.4 247.01,32.4 247.65,31.77 250.19,31.77 251.46,33.04 IC43.22 | D4.C 225.43,66.69 241.94,66.69 243.84,64.78 246.38,64.78 IC44.4
DRVSELB\
  Top 0.254: 258.44,142.89 258.44,123.2 264.16,117.49 R4.1 | IC45.22 258.44,142.89 | 258.44,142.89 258.44,164.48 IC46.4
  Bottom 0.254: IC39.22 234.95,144.79 235.59,144.16 247.01,144.16 247.65,143.52 250.19,143.52 251.46,144.79 IC45.22 | D8.C 225.43,178.45 241.94,178.45 243.84,176.54 246.38,176.54 IC46.4
GND  (1 unrouted)
  Top 0.254: G1.- 234.31,81.93 234.31,83.2 G1.-@1 | G2.-@1 262.25,83.2 262.25,81.93 G2.- 262.25,80.66 262.25,75.58 IC44.7 249.56,62.88 249.56,46.37 IC42.16 | RF08A.31 223.52,46.37 222.25,47.64 222.25,53.99 223.52,55.26 RF08A.39 | RF08B.31 223.52,158.13 222.25,159.4 222.25,165.75 223.52,167.02 RF08B.39 | G4.-@1 262.25,194.96 262.25,193.69 G4.- 253.37,183.53 253.37,178.45 IC46.7 251.46,176.54 | G3.-@1 234.31,194.96 234.31,193.69 G3.- 251.46,176.54 | 251.46,176.54 250.19,175.27 250.19,158.76 IC39.16
  Bottom 0.254: G1.- 250.19,66.06 IC44.7 | IC43.16 269.24,45.73 267.97,44.47 251.46,44.47 250.19,45.73 IC42.16 236.22,45.73 234.95,47.01 225.43,47.01 224.16,45.73 RF08A.31 | IC45.16 270.51,157.49 269.24,156.22 251.46,156.22 250.19,157.49 IC39.16 236.22,157.49 234.95,158.76 225.43,158.76 224.16,157.49 RF08B.31
MEMSUPPLY  (1 unrouted)
  Top 0.508: IC45.32 255.91,118.76 255.91,118.12 254.63,116.86 R4.2 D6.C 233.04,117.49 233.04,118.76 IC39.32 236.22,121.94 D5.C | IC43.32 254,7.63 254,7 252.09,5.09 R3.2 D1.C 233.04,5.73 233.04,7 IC42.32 236.22,10.18 D2.C
  Bottom 0.508: D5.C 238.76,162.57 IC46.14 246.38,162.57 247.65,161.3 262.89,161.3 D7.C | D2.C 238.76,50.81 IC44.14 246.38,50.81 247.65,49.55 262.89,49.55 D3.C
N$18
  Top 0.254: IC44.3 250.82,57.8 250.82,59.07 IC44.5 252.09,61.61 252.09,62.88 IC44.6
N$35
  Top 0.254: IC44.1 252.09,51.45 252.09,52.72 IC44.2
  Bottom 0.254: JP1.2 233.68,54.62 248.92,54.62 250.19,53.36 IC44.2
N$36
  Top 0.254: D7.A G4.+@1 267.33,173.37 267.33,174.64 G4.+@2 | G4.+ 258.44,173.37 258.44,174.64 G4.+@3
  Bottom 0.254: G4.+ 260.35,174 261.62,174 G4.+@4 264.16,174 265.43,174 G4.+@1
N$38
  Top 0.254: IC46.3 250.82,169.56 250.82,170.83 IC46.5 252.09,173.37 252.09,174.64 IC46.6
N$39
  Top 0.254: IC46.1 252.09,163.21 252.09,164.48 IC46.2
  Bottom 0.254: JP2.2 233.68,166.38 248.92,166.38 250.19,165.11 IC46.2
N$41
  Top 0.254: D5.A G3.+@1 239.4,173.37 239.4,174.64 G3.+@2 | G3.+ 230.5,173.37 230.5,174.64 G3.+@3
  Bottom 0.254: G3.+ 232.41,174 233.68,174 G3.+@4 236.22,174 237.49,174 G3.+@1
N$130
  Top 0.254: D3.A G2.+@1 267.33,61.61 267.33,62.88 G2.+@2 | G2.+ 258.44,61.61 258.44,62.88 G2.+@3
  Bottom 0.254: G2.+ 260.35,62.24 261.62,62.24 G2.+@4 264.16,62.24 265.43,62.24 G2.+@1
N$131
  Top 0.254: D2.A G1.+@1 239.4,61.61 239.4,62.88 G1.+@2 | G1.+ 230.5,61.61 230.5,62.88 G1.+@3
  Bottom 0.254: G1.+ 232.41,62.24 233.68,62.24 G1.+@4 236.22,62.24 237.49,62.24 G1.+@1
VCC  (1 unrouted)
  Top 0.508: D6.A 222.25,116.86 220.98,118.12 RF08B.2 | D1.A 222.25,5.09 220.98,6.36 RF08A.2
WE\  (1 unrouted)
  Bottom 0.254: RF08A.8 221.62,15.26 222.88,13.99 224.16,13.99 224.79,14.62 231.78,14.62 232.41,15.26 IC42.29 246.38,15.26 247.65,13.99 250.19,13.99 250.82,14.62 253.37,14.62 254,15.26 IC43.29 | RF08B.8 221.62,127.02 222.88,125.75 224.16,125.75 224.79,126.38 231.78,126.38 232.41,127.02 IC39.29 246.38,127.02 247.65,125.75 250.19,125.75 250.82,126.38 254.63,126.38 255.27,127.02 IC45.29
WRITING  (1 unrouted)
  Bottom 0.254: RF08A.18 221.62,27.96 222.88,26.69 224.16,26.69 224.79,27.32 231.78,27.32 232.41,27.96 IC42.24 245.11,27.96 246.38,26.69 250.19,26.69 250.82,27.32 253.37,27.32 254,27.96 IC43.24 | RF08B.18 221.62,139.71 222.88,138.44 224.16,138.44 224.79,139.08 231.78,139.08 232.41,139.71 IC39.24 245.11,139.71 246.38,138.44 250.19,138.44 250.82,139.08 254.63,139.08 255.27,139.71 IC45.24

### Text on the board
Bottom: RS08 | VRS | RF08 Debug | VRS | RS08 | VRS | RF08 | VRS
tPlace: RF08 | VRS
tValues: RF08 Debug | VRS | RS08 | VRS | RS08 | VRS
